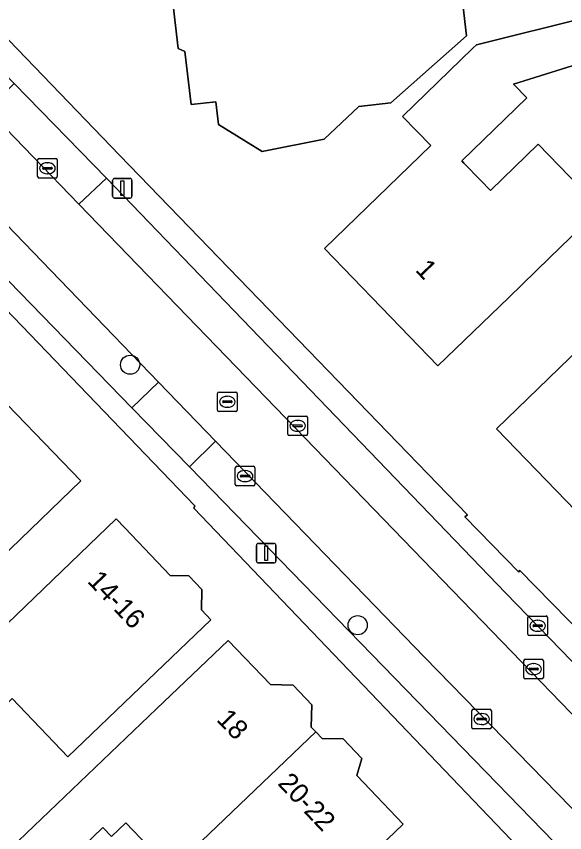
# Model space of a CAD drawing. Extents: x 161772 to 163126, y 383092 to 383917.
# Drawn here: x 162141.48 to 162169.48, y 383411.71 to 383453.39 of the extents above; entities that cross this region are included whole.
import ezdxf

# ---------------------------------------------------------------- set-up
doc = ezdxf.new("R2010")
doc.units = 0
for name, color, linetype in [('IMGEO_Boom', 7, 'Continuous'), ('IMGEO_Brandkraan', 7, 'Continuous'), ('IMGEO_Erf', 7, 'Continuous'), ('IMGEO_Kolk', 7, 'Continuous'), ('IMGEO_Lichtmast', 7, 'Continuous'), ('IMGEO_Pand', 7, 'Continuous'), ('IMGEO_Pand_nummerreeks', 7, 'Continuous'), ('IMGEO_Parkeervlak_open', 7, 'Continuous'), ('IMGEO_Rijbaan_lokaal_open', 7, 'Continuous'), ('IMGEO_Rioolput', 7, 'Continuous'), ('IMGEO_Voetpad_gesloten', 7, 'Continuous'), ('IMGEO_Voetpad_open', 7, 'Continuous')]:
    doc.layers.add(name, color=color, linetype=linetype)

msp = doc.modelspace()

# ---------------------------------------------------------------- linework, layer by layer
at = {"layer": 'IMGEO_Boom'}
for centre in [(162147.29, 383435.6), (162158.91, 383422.302)]:
    msp.add_circle(centre, 0.489, dxfattribs=at)
at = {"layer": 'IMGEO_Brandkraan'}
for p, q in [((162167.6, 383421.846), (162167.6, 383422.698)), ((162167.675, 383422.772), (162168.527, 383422.772)), ((162168.601, 383422.698), (162168.601, 383421.846)), ((162167.859, 383422.266), (162167.859, 383422.278)), ((162167.902, 383422.315), (162168.3, 383422.315)), ((162168.088, 383422.552), (162168.113, 383422.552)), ((162168.343, 383422.278), (162168.343, 383422.266)), ((162168.297, 383422.229), (162167.899, 383422.229)), ((162168.111, 383421.992), (162168.086, 383421.992)), ((162168.527, 383421.772), (162167.675, 383421.772))]:
    msp.add_line(p, q, dxfattribs=at)
for points in [[(162167.6, 383421.846), (162167.6, 383422.698)], [(162167.675, 383422.772), (162168.527, 383422.772)], [(162168.601, 383422.698), (162168.601, 383421.846)], [(162168.527, 383421.772), (162167.675, 383421.772)]]:
    msp.add_lwpolyline(points, dxfattribs=at)
for centre, radius, start, end in [((162167.677, 383422.696), 0.0765, 91.552, 178.448), ((162167.677, 383422.696), 0.0765, 91.552, 178.448), ((162168.525, 383422.696), 0.0765, 1.552, 88.448), ((162168.525, 383422.696), 0.0765, 1.552, 88.448), ((162167.899, 383422.275), 0.0403, 85.8775, 175.7526), ((162167.896, 383422.265), 0.0366, 178.938, 274.7102), ((162168.3, 383422.272), 0.043, 264.8664, 352.4533), ((162168.304, 383422.277), 0.0386, 1.7309, 96.639), ((162167.677, 383421.848), 0.0765, 181.552, 268.448), ((162167.677, 383421.848), 0.0765, 181.552, 268.448), ((162168.525, 383421.848), 0.0765, 271.552, 358.448), ((162168.525, 383421.848), 0.0765, 271.552, 358.448)]:
    msp.add_arc(centre, radius, start, end, dxfattribs=at)
for centre, major_axis, ratio, start_param, end_param in [((162168.087, 383422.272), (-0.387, 0.002), 0.722429, 4.712389, 7.853982), ((162168.112, 383422.272), (-0.39, 0.002), 0.717154, 1.570796, 4.712389)]:
    msp.add_ellipse(centre, major_axis=major_axis, ratio=ratio, start_param=start_param, end_param=end_param, dxfattribs=at)
at = {"layer": 'IMGEO_Erf'}
for points in [[(162184.032, 383393.274), (162150.539, 383428.274), (162150.594, 383428.39), (162124.921, 383455.092), (162125.07, 383455.226), (162117.429, 383462.692), (162117.208, 383462.523), (162111.823, 383466.516), (162107.132, 383469.149), (162104.903, 383470.142), (162100.337, 383471.381), (162086.524, 383472.415)], [(162162.359, 383470.605), (162164.463, 383452.395), (162160.609, 383448.978), (162158.975, 383448.789), (162157.206, 383447.12), (162154.031, 383446.483), (162151.807, 383447.867), (162151.673, 383449.025), (162150.402, 383448.878), (162150.087, 383451.599), (162149.743, 383451.748), (162148.317, 383464.091)], [(162124.151, 383469.777), (162146.748, 383446.299), (162164.511, 383427.931), (162164.384, 383427.827), (162167.143, 383425.007), (162167.165, 383425.116), (162173.798, 383418.361)], [(162170.557, 383427.608), (162165.994, 383432.321), (162173.478, 383439.567)]]:
    msp.add_lwpolyline(points, dxfattribs=at)
for points in [[(162164.225, 383446.005), (162164.33, 383445.896), (162165.196, 383445.002), (162165.69, 383444.492), (162168.133, 383446.857), (162171.31, 383443.576), (162168.726, 383441.075), (162166.604, 383439.02), (162163.011, 383435.542), (162157.215, 383441.528), (162162.647, 383446.787), (162161.204, 383448.278), (162164.797, 383451.756), (162164.977, 383451.931), (162170.709, 383453.368), (162171.232, 383451.28), (162166.858, 383449.93), (162167.546, 383449.22)], [(162130.895, 383426.573), (162127.969, 383429.591), (162130.278, 383431.829), (162128.038, 383434.143), (162130.843, 383436.864), (162134.432, 383440.344), (162139.601, 383435.013), (162144.772, 383429.681), (162141.183, 383426.201), (162138.367, 383423.47), (162133.201, 383428.808)], [(162141.265, 383418.564), (162139.695, 383417.062), (162139.997, 383416.747), (162140.4, 383416.326), (162135.823, 383411.946), (162133.544, 383414.327), (162133.113, 383414.777), (162146.571, 383427.738), (162147.013, 383427.277), (162149.344, 383424.842), (162150.281, 383424.822), (162150.955, 383424.117), (162150.933, 383423.083), (162151.416, 383422.579), (162147.804, 383419.122), (162144.106, 383415.583)], [(162141.599, 383411.298), (162148.641, 383418.038), (162152.289, 383421.529), (162154.452, 383419.269), (162155.608, 383419.244), (162156.565, 383418.243), (162156.54, 383417.104), (162156.778, 383416.856), (162157.097, 383416.523), (162158.167, 383416.499), (162159.123, 383415.5), (162158.868, 383414.626), (162161.237, 383412.151), (162157.625, 383408.694), (162148.176, 383399.65), (162145.752, 383402.183), (162149.458, 383405.729), (162147.516, 383407.758), (162149.51, 383409.667), (162149.381, 383409.802), (162147.077, 383412.209), (162146.344, 383411.508), (162145.904, 383411.968), (162143.323, 383409.497)]]:
    msp.add_lwpolyline(points, close=True, dxfattribs=at)
at = {"layer": 'IMGEO_Kolk'}
for p, q in [((162142.567, 383445.204), (162142.567, 383446.056)), ((162142.642, 383446.13), (162143.494, 383446.13)), ((162143.568, 383446.056), (162143.568, 383445.204)), ((162142.826, 383445.624), (162142.826, 383445.636)), ((162142.869, 383445.673), (162143.267, 383445.673)), ((162143.055, 383445.91), (162143.08, 383445.91)), ((162143.31, 383445.636), (162143.31, 383445.624)), ((162143.264, 383445.587), (162142.866, 383445.587)), ((162143.078, 383445.35), (162143.053, 383445.35)), ((162143.494, 383445.13), (162142.642, 383445.13)), ((162155.345, 383432.055), (162155.345, 383432.907)), ((162155.42, 383432.981), (162156.272, 383432.981)), ((162155.833, 383432.761), (162155.858, 383432.761)), ((162156.346, 383432.907), (162156.346, 383432.055)), ((162155.604, 383432.475), (162155.604, 383432.487)), ((162156.042, 383432.438), (162155.644, 383432.438)), ((162155.647, 383432.524), (162156.045, 383432.524)), ((162156.088, 383432.487), (162156.088, 383432.475)), ((162156.272, 383431.981), (162155.42, 383431.981)), ((162155.856, 383432.201), (162155.831, 383432.201)), ((162152.662, 383429.49), (162152.662, 383430.342)), ((162152.737, 383430.416), (162153.589, 383430.416)), ((162153.15, 383430.196), (162153.175, 383430.196)), ((162153.663, 383430.342), (162153.663, 383429.49)), ((162152.921, 383429.91), (162152.921, 383429.922)), ((162153.359, 383429.873), (162152.961, 383429.873)), ((162152.964, 383429.959), (162153.362, 383429.959)), ((162153.405, 383429.922), (162153.405, 383429.91)), ((162153.589, 383429.416), (162152.737, 383429.416)), ((162153.173, 383429.636), (162153.148, 383429.636)), ((162167.391, 383419.635), (162167.391, 383420.487)), ((162167.466, 383420.561), (162168.318, 383420.561)), ((162167.879, 383420.341), (162167.904, 383420.341)), ((162168.392, 383420.487), (162168.392, 383419.635)), ((162167.65, 383420.055), (162167.65, 383420.067)), ((162168.088, 383420.018), (162167.69, 383420.018)), ((162167.693, 383420.104), (162168.091, 383420.104)), ((162167.902, 383419.781), (162167.877, 383419.781)), ((162168.134, 383420.067), (162168.134, 383420.055)), ((162168.318, 383419.561), (162167.466, 383419.561)), ((162164.738, 383417.085), (162164.738, 383417.937)), ((162164.813, 383418.011), (162165.665, 383418.011)), ((162165.226, 383417.791), (162165.251, 383417.791)), ((162165.739, 383417.937), (162165.739, 383417.085)), ((162164.997, 383417.505), (162164.997, 383417.517)), ((162165.435, 383417.468), (162165.037, 383417.468)), ((162165.04, 383417.554), (162165.438, 383417.554)), ((162165.481, 383417.517), (162165.481, 383417.505)), ((162165.665, 383417.011), (162164.813, 383417.011)), ((162165.249, 383417.231), (162165.224, 383417.231))]:
    msp.add_line(p, q, dxfattribs=at)
for points in [[(162142.567, 383445.204), (162142.567, 383446.056)], [(162142.642, 383446.13), (162143.494, 383446.13)], [(162143.568, 383446.056), (162143.568, 383445.204)], [(162143.494, 383445.13), (162142.642, 383445.13)], [(162155.345, 383432.055), (162155.345, 383432.907)], [(162155.42, 383432.981), (162156.272, 383432.981)], [(162156.346, 383432.907), (162156.346, 383432.055)], [(162156.272, 383431.981), (162155.42, 383431.981)], [(162152.662, 383429.49), (162152.662, 383430.342)], [(162152.737, 383430.416), (162153.589, 383430.416)], [(162153.663, 383430.342), (162153.663, 383429.49)], [(162153.589, 383429.416), (162152.737, 383429.416)], [(162167.391, 383419.635), (162167.391, 383420.487)], [(162167.466, 383420.561), (162168.318, 383420.561)], [(162168.392, 383420.487), (162168.392, 383419.635)], [(162168.318, 383419.561), (162167.466, 383419.561)], [(162164.738, 383417.085), (162164.738, 383417.937)], [(162164.813, 383418.011), (162165.665, 383418.011)], [(162165.739, 383417.937), (162165.739, 383417.085)], [(162165.665, 383417.011), (162164.813, 383417.011)]]:
    msp.add_lwpolyline(points, dxfattribs=at)
for centre, radius, start, end in [((162142.644, 383446.054), 0.0765, 91.552, 178.448), ((162142.644, 383446.054), 0.0765, 91.552, 178.448), ((162143.492, 383446.054), 0.0765, 1.552, 88.448), ((162143.492, 383446.054), 0.0765, 1.552, 88.448), ((162142.866, 383445.633), 0.0403, 85.8775, 175.7526), ((162142.863, 383445.623), 0.0366, 178.938, 274.7102), ((162143.267, 383445.63), 0.043, 264.8664, 352.4533), ((162143.271, 383445.635), 0.0386, 1.7309, 96.639), ((162142.644, 383445.206), 0.0765, 181.552, 268.448), ((162142.644, 383445.206), 0.0765, 181.552, 268.448), ((162143.492, 383445.206), 0.0765, 271.552, 358.448), ((162143.492, 383445.206), 0.0765, 271.552, 358.448), ((162155.422, 383432.905), 0.0765, 91.552, 178.448), ((162155.422, 383432.905), 0.0765, 91.552, 178.448), ((162156.27, 383432.905), 0.0765, 1.552, 88.448), ((162156.27, 383432.905), 0.0765, 1.552, 88.448), ((162155.644, 383432.484), 0.0403, 85.8775, 175.7526), ((162155.641, 383432.474), 0.0366, 178.938, 274.7102), ((162156.045, 383432.481), 0.043, 264.8664, 352.4533), ((162156.049, 383432.486), 0.0386, 1.7309, 96.639), ((162155.422, 383432.057), 0.0765, 181.552, 268.448), ((162155.422, 383432.057), 0.0765, 181.552, 268.448), ((162156.27, 383432.057), 0.0765, 271.552, 358.448), ((162156.27, 383432.057), 0.0765, 271.552, 358.448), ((162152.739, 383430.34), 0.0765, 91.552, 178.448), ((162152.739, 383430.34), 0.0765, 91.552, 178.448), ((162153.587, 383430.34), 0.0765, 1.552, 88.448), ((162153.587, 383430.34), 0.0765, 1.552, 88.448), ((162152.961, 383429.919), 0.0403, 85.8775, 175.7526), ((162152.958, 383429.909), 0.0366, 178.938, 274.7102), ((162153.362, 383429.916), 0.043, 264.8664, 352.4533), ((162153.366, 383429.921), 0.0386, 1.7309, 96.639), ((162152.739, 383429.492), 0.0765, 181.552, 268.448), ((162152.739, 383429.492), 0.0765, 181.552, 268.448), ((162153.587, 383429.492), 0.0765, 271.552, 358.448), ((162153.587, 383429.492), 0.0765, 271.552, 358.448), ((162167.468, 383420.485), 0.0765, 91.552, 178.448), ((162167.468, 383420.485), 0.0765, 91.552, 178.448), ((162168.316, 383420.485), 0.0765, 1.552, 88.448), ((162168.316, 383420.485), 0.0765, 1.552, 88.448), ((162167.69, 383420.064), 0.0403, 85.8775, 175.7526), ((162167.687, 383420.054), 0.0366, 178.938, 274.7102), ((162168.091, 383420.061), 0.043, 264.8664, 352.4533), ((162168.095, 383420.066), 0.0386, 1.7309, 96.639), ((162167.468, 383419.637), 0.0765, 181.552, 268.448), ((162167.468, 383419.637), 0.0765, 181.552, 268.448), ((162168.316, 383419.637), 0.0765, 271.552, 358.448), ((162168.316, 383419.637), 0.0765, 271.552, 358.448), ((162164.815, 383417.935), 0.0765, 91.552, 178.448), ((162164.815, 383417.935), 0.0765, 91.552, 178.448), ((162165.663, 383417.935), 0.0765, 1.552, 88.448), ((162165.663, 383417.935), 0.0765, 1.552, 88.448), ((162165.037, 383417.514), 0.0403, 85.8775, 175.7526), ((162165.034, 383417.504), 0.0366, 178.938, 274.7102), ((162165.438, 383417.511), 0.043, 264.8664, 352.4533), ((162165.442, 383417.516), 0.0386, 1.7309, 96.639), ((162164.815, 383417.087), 0.0765, 181.552, 268.448), ((162164.815, 383417.087), 0.0765, 181.552, 268.448), ((162165.663, 383417.087), 0.0765, 271.552, 358.448), ((162165.663, 383417.087), 0.0765, 271.552, 358.448)]:
    msp.add_arc(centre, radius, start, end, dxfattribs=at)
for centre, major_axis, ratio, start_param, end_param in [((162143.054, 383445.63), (-0.387, 0.002), 0.722429, 4.712389, 7.853982), ((162143.079, 383445.63), (-0.39, 0.002), 0.717154, 1.570796, 4.712389), ((162155.832, 383432.481), (-0.387, 0.002), 0.722429, 4.712389, 7.853982), ((162155.857, 383432.481), (-0.39, 0.002), 0.717154, 1.570796, 4.712389), ((162153.149, 383429.916), (-0.387, 0.002), 0.722429, 4.712389, 7.853982), ((162153.174, 383429.916), (-0.39, 0.002), 0.717154, 1.570796, 4.712389), ((162167.878, 383420.061), (-0.387, 0.002), 0.722429, 4.712389, 7.853982), ((162167.903, 383420.061), (-0.39, 0.002), 0.717154, 1.570796, 4.712389), ((162165.225, 383417.511), (-0.387, 0.002), 0.722429, 4.712389, 7.853982), ((162165.25, 383417.511), (-0.39, 0.002), 0.717154, 1.570796, 4.712389)]:
    msp.add_ellipse(centre, major_axis=major_axis, ratio=ratio, start_param=start_param, end_param=end_param, dxfattribs=at)
at = {"layer": 'IMGEO_Lichtmast'}
for p, q in [((162146.396, 383444.209), (162146.396, 383445.009)), ((162146.396, 383445.009), (162146.396, 383444.209)), ((162146.496, 383445.109), (162147.286, 383445.109)), ((162147.286, 383445.109), (162146.496, 383445.109)), ((162147.386, 383445.009), (162147.386, 383444.209)), ((162147.386, 383444.209), (162147.386, 383445.009)), ((162147.286, 383444.109), (162146.496, 383444.109)), ((162146.496, 383444.109), (162147.286, 383444.109)), ((162153.841, 383426.478), (162154.631, 383426.478)), ((162154.631, 383426.478), (162153.841, 383426.478)), ((162153.741, 383425.578), (162153.741, 383426.378)), ((162153.741, 383426.378), (162153.741, 383425.578)), ((162154.731, 383426.378), (162154.731, 383425.578)), ((162154.731, 383425.578), (162154.731, 383426.378)), ((162154.631, 383425.478), (162153.841, 383425.478)), ((162153.841, 383425.478), (162154.631, 383425.478))]:
    msp.add_line(p, q, dxfattribs=at)
for points in [[(162146.816, 383444.984), (162146.966, 383444.984), (162146.966, 383444.234), (162146.816, 383444.234), (162146.816, 383444.984)], [(162154.161, 383426.353), (162154.311, 383426.353), (162154.311, 383425.603), (162154.161, 383425.603), (162154.161, 383426.353)]]:
    msp.add_lwpolyline(points, dxfattribs=at)
for centre, start, end in [((162146.496, 383445.009), 90, 180), ((162146.496, 383445.009), 90, 180), ((162147.286, 383445.009), 0, 90), ((162147.286, 383445.009), 360, 90), ((162146.496, 383444.209), 180, 270), ((162146.496, 383444.209), 180, 270), ((162147.286, 383444.209), 270, 0), ((162147.286, 383444.209), 270, 0), ((162153.841, 383426.378), 90, 180), ((162153.841, 383426.378), 90, 180), ((162154.631, 383426.378), 0, 90), ((162154.631, 383426.378), 360, 90), ((162153.841, 383425.578), 180, 270), ((162153.841, 383425.578), 180, 270), ((162154.631, 383425.578), 270, 0), ((162154.631, 383425.578), 270, 0)]:
    msp.add_arc(centre, 0.1, start, end, dxfattribs=at)
at = {"layer": 'IMGEO_Pand'}
for points in [[(162146.604, 383471.326), (162146.818, 383469.572), (162147.668, 383469.671), (162148.317, 383464.091), (162149.743, 383451.748), (162150.087, 383451.599), (162150.402, 383448.878), (162151.673, 383449.025), (162151.807, 383447.867), (162154.031, 383446.483), (162157.206, 383447.12), (162158.975, 383448.789), (162160.609, 383448.978), (162164.463, 383452.395), (162162.359, 383470.605), (162158.258, 383469.52), (162158.172, 383470.271), (162157.768, 383470.224), (162157.593, 383471.738), (162157.845, 383471.767), (162157.771, 383472.402), (162154.902, 383472.07), (162154.816, 383472.815), (162146.542, 383471.859)], [(162171.31, 383443.576), (162168.133, 383446.857), (162165.69, 383444.492), (162165.196, 383445.002), (162164.33, 383445.896), (162164.225, 383446.005), (162167.546, 383449.22), (162166.858, 383449.93), (162171.232, 383451.28), (162170.709, 383453.368), (162164.977, 383451.931), (162164.797, 383451.756), (162161.204, 383448.278), (162162.647, 383446.787), (162157.215, 383441.528), (162163.011, 383435.542), (162166.604, 383439.02), (162168.726, 383441.075)], [(162176.417, 383438.34), (162180.832, 383442.615), (162181.299, 383443.067), (162178.433, 383445.988), (162176.781, 383444.387), (162176.26, 383443.883), (162174.274, 383441.959), (162172.668, 383440.404), (162173.478, 383439.567), (162165.994, 383432.321), (162170.557, 383427.608), (162178.946, 383435.729)], [(162139.601, 383435.013), (162133.201, 383428.808), (162138.367, 383423.47), (162141.183, 383426.201), (162144.772, 383429.681)], [(162147.804, 383419.122), (162151.416, 383422.579), (162150.933, 383423.083), (162150.955, 383424.117), (162150.281, 383424.822), (162149.344, 383424.842), (162147.013, 383427.277), (162146.571, 383427.738), (162133.113, 383414.777), (162133.544, 383414.327), (162135.823, 383411.946), (162140.4, 383416.326), (162139.997, 383416.747), (162139.695, 383417.062), (162141.265, 383418.564), (162144.106, 383415.583)], [(162149.381, 383409.802), (162156.778, 383416.856), (162156.54, 383417.104), (162156.565, 383418.243), (162155.608, 383419.244), (162154.452, 383419.269), (162152.289, 383421.529), (162148.641, 383418.038), (162141.599, 383411.298), (162143.323, 383409.497), (162145.904, 383411.968), (162146.344, 383411.508), (162147.077, 383412.209)], [(162149.381, 383409.802), (162149.51, 383409.667), (162147.516, 383407.758), (162149.458, 383405.729), (162145.752, 383402.183), (162148.176, 383399.65), (162157.625, 383408.694), (162161.237, 383412.151), (162158.868, 383414.626), (162159.123, 383415.5), (162158.167, 383416.499), (162157.097, 383416.523), (162156.778, 383416.856)]]:
    msp.add_lwpolyline(points, close=True, dxfattribs=at)
at = {"layer": 'IMGEO_Parkeervlak_open'}
for points in [[(162228.36, 383359.913), (162202.24, 383387.094), (162166.479, 383423.941), (162146.078, 383445.121), (162144.674, 383443.797), (162227.035, 383358.663)], [(162148.747, 383434.702), (162139.588, 383444.181), (162139.521, 383444.123), (162138.751, 383443.331), (162138.229, 383442.804), (162147.38, 383433.399)], [(162150.325, 383430.382), (162184.058, 383395.679), (162185.398, 383397.017), (162162.314, 383420.669), (162151.652, 383431.699)]]:
    msp.add_lwpolyline(points, close=True, dxfattribs=at)
at = {"layer": 'IMGEO_Rijbaan_lokaal_open'}
msp.add_lwpolyline([(162229.084, 383356.526), (162227.035, 383358.663), (162144.674, 383443.797), (162139.993, 383448.624), (162123.379, 383465.784), (162118.063, 383471.34), (162114.715, 383469.726), (162115.405, 383468.922), (162119.726, 383464.542), (162135.053, 383448.745), (162139.521, 383444.123), (162139.588, 383444.181), (162148.747, 383434.702), (162151.652, 383431.699), (162162.314, 383420.669), (162185.398, 383397.017), (162189.805, 383392.461), (162198.133, 383383.722), (162235.904, 383344.593), (162238.48, 383346.724)], close=True, dxfattribs=at)
at = {"layer": 'IMGEO_Rioolput'}
for p, q in [((162151.755, 383433.281), (162151.755, 383434.133)), ((162151.83, 383434.207), (162152.682, 383434.207)), ((162152.243, 383433.987), (162152.268, 383433.987)), ((162152.756, 383434.133), (162152.756, 383433.281)), ((162152.014, 383433.701), (162152.014, 383433.713)), ((162152.452, 383433.664), (162152.054, 383433.664)), ((162152.057, 383433.75), (162152.455, 383433.75)), ((162152.498, 383433.713), (162152.498, 383433.701)), ((162152.682, 383433.207), (162151.83, 383433.207)), ((162152.266, 383433.427), (162152.241, 383433.427))]:
    msp.add_line(p, q, dxfattribs=at)
for points in [[(162151.755, 383433.281), (162151.755, 383434.133)], [(162151.83, 383434.207), (162152.682, 383434.207)], [(162152.756, 383434.133), (162152.756, 383433.281)], [(162152.682, 383433.207), (162151.83, 383433.207)]]:
    msp.add_lwpolyline(points, dxfattribs=at)
for centre, radius, start, end in [((162151.832, 383434.131), 0.0765, 91.552, 178.448), ((162151.832, 383434.131), 0.0765, 91.552, 178.448), ((162152.68, 383434.131), 0.0765, 1.552, 88.448), ((162152.68, 383434.131), 0.0765, 1.552, 88.448), ((162152.054, 383433.71), 0.0403, 85.8775, 175.7526), ((162152.051, 383433.7), 0.0366, 178.938, 274.7102), ((162152.455, 383433.707), 0.043, 264.8664, 352.4533), ((162152.459, 383433.712), 0.0386, 1.7309, 96.639), ((162151.832, 383433.283), 0.0765, 181.552, 268.448), ((162151.832, 383433.283), 0.0765, 181.552, 268.448), ((162152.68, 383433.283), 0.0765, 271.552, 358.448), ((162152.68, 383433.283), 0.0765, 271.552, 358.448)]:
    msp.add_arc(centre, radius, start, end, dxfattribs=at)
for centre, major_axis, ratio, start_param, end_param in [((162152.242, 383433.707), (-0.387, 0.002), 0.722429, 4.712389, 7.853982), ((162152.267, 383433.707), (-0.39, 0.002), 0.717154, 1.570796, 4.712389)]:
    msp.add_ellipse(centre, major_axis=major_axis, ratio=ratio, start_param=start_param, end_param=end_param, dxfattribs=at)
at = {"layer": 'IMGEO_Voetpad_gesloten'}
for points in [[(162113.593, 383471.954), (162110.865, 383472.685), (162104.678, 383474.608), (162100.337, 383471.381), (162104.903, 383470.142), (162107.132, 383469.149), (162111.823, 383466.516), (162117.208, 383462.523), (162117.429, 383462.692), (162125.07, 383455.226), (162124.921, 383455.092), (162150.594, 383428.39), (162150.539, 383428.274), (162184.032, 383393.274), (162186.711, 383390.706), (162198.139, 383378.591), (162198.256, 383378.698), (162215.237, 383360.897), (162231.771, 383343.74), (162232.967, 383342.555), (162234.371, 383341.095)], [(162238.48, 383346.724), (162239.996, 383345.054), (162240.594, 383344.436), (162243.372, 383346.601), (162237.143, 383353.041), (162225.52, 383365.058), (162192.872, 383399.214), (162192.761, 383399.098), (162187.816, 383404.232), (162187.734, 383404.146), (162182.533, 383409.335), (162182.621, 383409.404), (162173.894, 383418.482), (162173.798, 383418.361), (162167.165, 383425.116), (162167.143, 383425.007), (162164.384, 383427.827), (162164.511, 383427.931), (162146.748, 383446.299), (162124.151, 383469.777)], [(162232.741, 383345.129), (162188.472, 383391.139), (162184.058, 383395.679), (162150.325, 383430.382), (162147.38, 383433.399), (162138.229, 383442.804), (162138.751, 383443.331), (162134.258, 383447.982), (162135.053, 383448.745), (162119.726, 383464.542), (162118.937, 383463.776), (162114.594, 383468.182), (162115.405, 383468.922), (162114.715, 383469.726)], [(162126.398, 383465.384), (162141.362, 383449.954), (162146.078, 383445.121), (162166.479, 383423.941), (162202.24, 383387.094), (162228.36, 383359.913), (162230.382, 383357.811), (162237.721, 383350.184)]]:
    msp.add_lwpolyline(points, dxfattribs=at)
at = {"layer": 'IMGEO_Voetpad_open'}
for points in [[(162139.993, 383448.624), (162144.674, 383443.797), (162146.078, 383445.121), (162141.362, 383449.954)], [(162147.38, 383433.399), (162150.325, 383430.382), (162151.652, 383431.699), (162148.747, 383434.702)]]:
    msp.add_lwpolyline(points, close=True, dxfattribs=at)

# ---------------------------------------------------------------- texts
at = {"layer": 'IMGEO_Pand_nummerreeks'}
for s, rotation, p in [('1', 314.0774, (162161.811, 383440.404)), ('14-16', 313.5331, (162145.065, 383424.517)), ('18', 313.8495, (162151.66, 383417.448)), ('20-22', 313.4623, (162154.784, 383414.192))]:
    msp.add_text(s, height=1, rotation=rotation, dxfattribs=at).set_placement(p)

doc.saveas('drawing.dxf')
